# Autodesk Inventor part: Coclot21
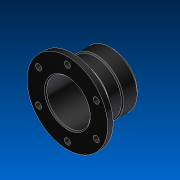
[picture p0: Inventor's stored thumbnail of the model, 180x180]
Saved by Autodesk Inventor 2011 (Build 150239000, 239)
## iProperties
Created: 2011-05
Part Number: Coclot21
Document SubType Name: Modeling
Designer: 904Chiaki
Density: 1 g/cm^3
Mass: 303.621 g
Surface Area: 728.501 cm^2
Volume: 303.621 cm^3
Author: 904Chiaki
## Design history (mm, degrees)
sketch "Sketch1"
  geometry: L1 (-16.544, 31.721)-(-16.544, -18.279); L2 (23.456, 72.423)-(23.456, -10.577); L3 (23.456, 72.423)-(33.456, 72.423); L4 (33.456, -0.577)-(57.456, -0.577); L5 (57.456, -0.577)-(57.456, -10.577); L6 (57.456, -10.577)-(23.456, -10.577); L7 (33.456, 19.423)-(31.456, 19.423); L8 (33.456, 72.423)-(33.456, 40.654); L9 (33.456, 19.423)-(33.456, 0.423); L10 (33.456, 0.423)-(32.956, 0.423); L11 (32.956, 0.423)-(32.956, -0.577); L12 (32.956, -0.577)-(33.456, -0.577); L13 (31.456, 19.423)-(31.456, 40.654); L14 (33.456, 40.654)-(31.456, 40.654); 1 further point
  constraints: 28 end point
  dimensions: "d0" = 50 distance of L1.start L1.end; "d1" = 40 distance between parallel lines of L1 L2; "d2" = 83 distance of L2.start L2.end; "d5" = 10 distance of L2.start L3.end; "d6" = 73 distance of L3.end L4.start; "d14" = 2 distance of L7.start L7.end; "d15" = 0.5 distance of L9.end L10.end; "d16" = 1 distance between parallel lines of L4 L10
revolve "Revolution1" sketch "Sketch1" stored, may be unused: angle "d17" = 90 deg
chamfer "Chamfer1" distance "d18" = 5; stored, may be unused: second distance "d19" = 2, angle "d20" = 45 deg
chamfer "Chamfer2" distance "d21" = 0.5; stored, may be unused: second distance "d22" = 2, angle "d23" = 45 deg
chamfer "Chamfer4" distance "d31" = 2; stored, may be unused: second distance "d32" = 2, angle "d33" = 45 deg
chamfer "Chamfer5" distance "d34" = 0.5; stored, may be unused: second distance "d35" = 2, angle "d36" = 45 deg
workplane "Work Plane5"
node "Hole2"
chamfer "Chamfer6" distance "d45" = 2; stored, may be unused: second distance "d46" = 2, angle "d47" = 45 deg
body "Solid1"
sketch "Sketch3"
  geometry: 6 further points
hole "Hole1" sketch "Sketch3" diameter "d38" = 11; stored, may be unused: countersink angle "d42" = 90 deg, drill point angle "d44" = 0 deg; dims "d39" = 6, "d40" = 4, "d41" = 2, "d43" = 8
